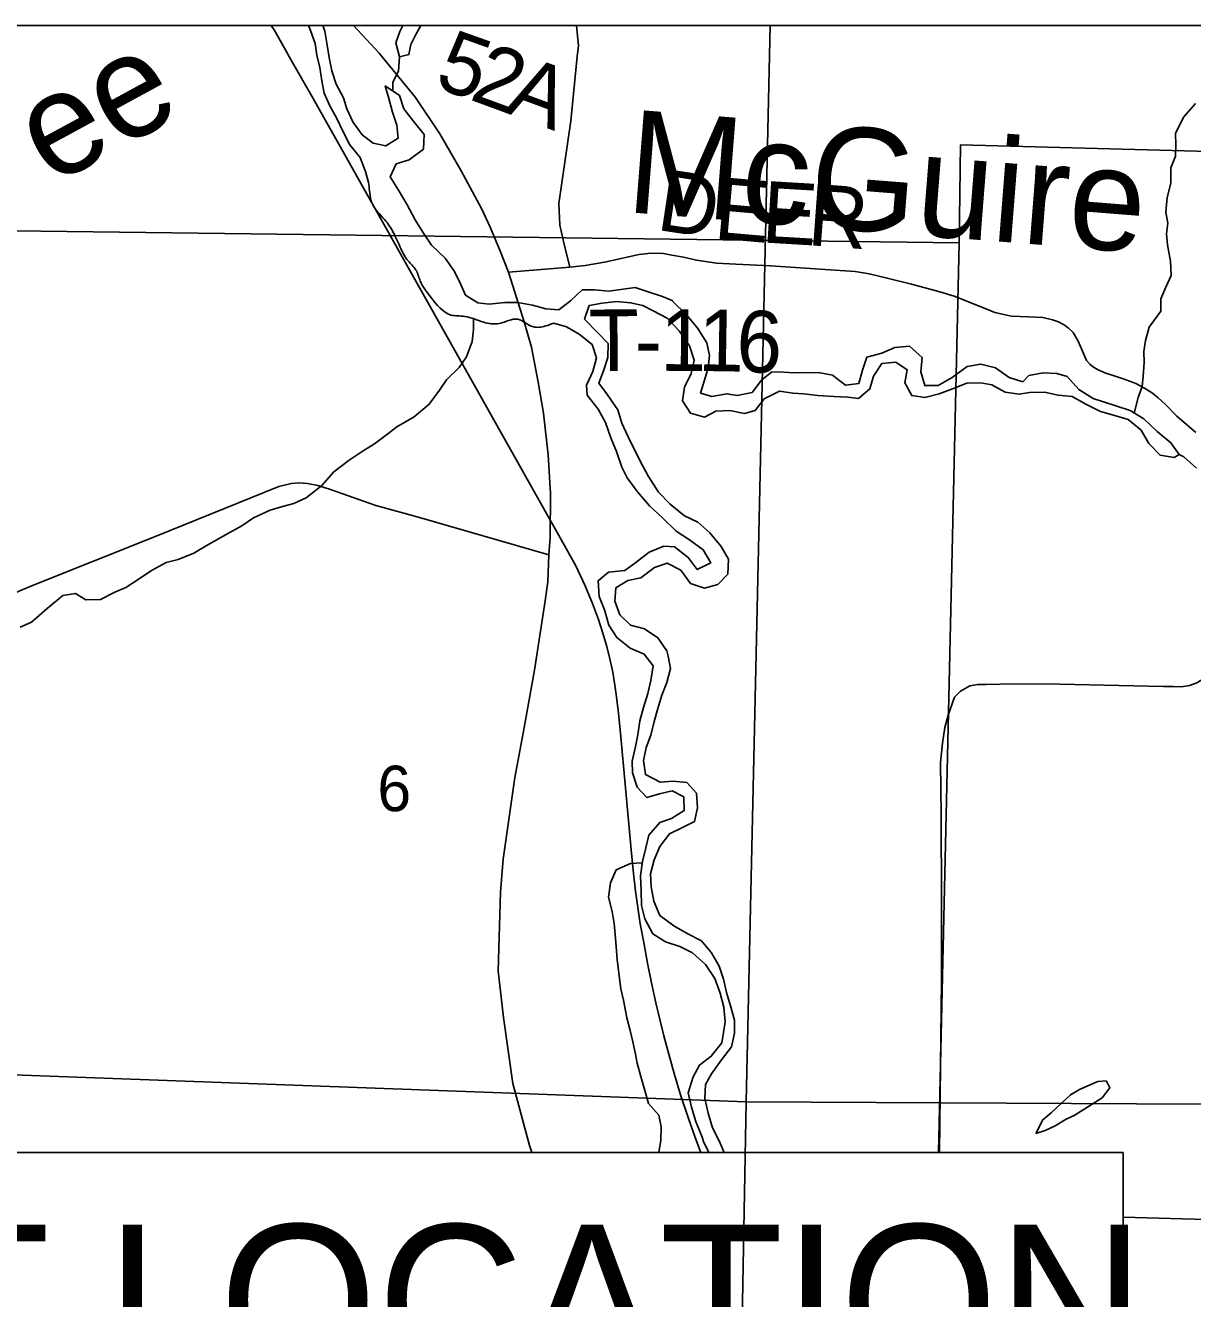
# Model space of a CAD drawing. Extents: x -19.9 to 41.9, y 0 to 32.3.
# Drawn here: x 3.386 to 4.462, y 19.727 to 20.9 of the extents above; entities that cross this region are included whole.
import ezdxf

# ---------------------------------------------------------------- set-up
doc = ezdxf.new("R2010")
doc.units = 0
for name, color, linetype in [('GM_X_Corporation', 7, 'Continuous'), ('GM_X_County_Road', 7, 'Continuous'), ('GM_X_County_Road_Text', 7, 'Continuous'), ('GM_X_Major_River', 7, 'Continuous'), ('GM_X_Major_River_Text', 7, 'Continuous'), ('GM_X_Minor_Lake', 7, 'Continuous'), ('GM_X_Minor_River', 7, 'Continuous'), ('GM_X_Rail_Line', 7, 'Continuous'), ('GM_X_Section', 7, 'Continuous'), ('GM_X_Section_Text', 7, 'Continuous'), ('GM_X_State_Route', 7, 'Continuous'), ('GM_X_Township_Road', 7, 'Continuous'), ('GM_X_Township_Road_Text', 7, 'Continuous'), ('SH_Data', 7, 'Continuous'), ('SH_Text', 7, 'Continuous')]:
    doc.layers.add(name, color=color, linetype=linetype)

msp = doc.modelspace()

# ---------------------------------------------------------------- linework, layer by layer
at = {"layer": 'GM_X_Corporation'}
for points in [[(8.9, 17.8974), (8.9, 20.9), (2.1, 20.9), (2.1, 17.918), (2.4715, 17.9106), (2.973, 17.9007), (3.7505, 17.884), (3.984, 17.879), (4.2613, 17.8672), (4.9169, 17.8392), (5.0192, 17.8403), (5.0257, 17.9637), (5.4954, 17.9559), (5.761, 17.9543), (5.9048, 17.9534), (6.2397, 17.9517), (6.2497, 17.9517), (6.3069, 17.9505), (6.7, 17.9422), (6.9468, 17.937), (7.3858, 17.9277), (7.5529, 17.9242), (7.9072, 17.9171)], [(4.0724, 20.9), (3.0583, 20.9), (3.0491, 19.9448), (4.0503, 19.9079)], [(4.5578, 20.9), (4.0724, 20.9), (4.0503, 19.9079), (5.0703, 19.9026), (5.0685, 20), (5.0885, 20.8933)], [(3.0491, 19.9448), (4.0503, 19.9079), (4.0319, 18.9009), (3.0393, 18.921)], [(4.0503, 19.9079), (5.0703, 19.9026), (5.0551, 18.9965), (5.0537, 18.8813), (4.0319, 18.9009)]]:
    msp.add_lwpolyline(points, close=True, dxfattribs=at)
msp.add_lwpolyline([(2.973, 17.9007), (3.7505, 17.884), (3.984, 17.879), (4.2613, 17.8672), (4.9169, 17.8392), (5.0192, 17.8403), (5.0257, 17.9637), (5.4954, 17.9559), (5.761, 17.9543), (5.9048, 17.9534), (6.2397, 17.9517), (6.2497, 17.9517), (6.3069, 17.9505), (6.7, 17.9422), (6.9468, 17.937), (7.3858, 17.9277), (7.5529, 17.9242), (7.9072, 17.9171), (7.9208, 18.3004), (7.9387, 18.9418), (7.9433, 19.1981), (7.9567, 19.9408), (7.9833, 20.9), (2.1, 20.9)], dxfattribs=at)
at = {"layer": 'GM_X_County_Road'}
msp.add_line((3.8935, 20.9), (3.894, 20.8998), dxfattribs=at)
for points in [[(3.894, 20.9), (3.894, 20.8998), (3.8956, 20.8815), (3.8946, 20.8713), (3.8887, 20.812), (3.8776, 20.736), (3.8784, 20.716), (3.883, 20.6958), (3.8867, 20.6812)], [(3.8867, 20.6812), (3.8877, 20.6773), (3.8313, 20.6725)], [(4.2286, 19.8611), (4.2303, 20.0199), (4.2305, 20.0932), (4.2301, 20.172), (4.2294, 20.2206), (4.2313, 20.2385), (4.2335, 20.2529), (4.2365, 20.2644), (4.2423, 20.281), (4.248, 20.2864), (4.2564, 20.2913), (4.264, 20.2926), (4.2714, 20.2927), (4.2841, 20.293), (4.3257, 20.2932), (4.4349, 20.2907), (4.4439, 20.2907), (4.4516, 20.2903), (4.4589, 20.2915), (4.4657, 20.294), (4.4728, 20.2984), (4.495, 20.3155), (4.529, 20.3478)]]:
    msp.add_lwpolyline(points, dxfattribs=at)
at = {"layer": 'GM_X_Major_River'}
for points in [[(3.6467, 20.9), (3.6487, 20.8955), (3.6531, 20.8834), (3.6544, 20.8725), (3.6572, 20.8611), (3.659, 20.849), (3.6614, 20.8377), (3.6666, 20.826), (3.6729, 20.8143), (3.6788, 20.8019), (3.685, 20.7899), (3.6944, 20.7783)], [(3.8777, 20.638), (3.8655, 20.6389), (3.8533, 20.6421), (3.8399, 20.6445), (3.8278, 20.6447), (3.8133, 20.643), (3.803, 20.6443), (3.7915, 20.6513), (3.7856, 20.6645), (3.7809, 20.6743), (3.7727, 20.6855), (3.7603, 20.6975), (3.7522, 20.7095), (3.7451, 20.7207), (3.7377, 20.7346), (3.7298, 20.7482), (3.722, 20.7605), (3.7275, 20.7724), (3.7396, 20.776), (3.7528, 20.7861), (3.7533, 20.7994), (3.7432, 20.8121), (3.7347, 20.8233), (3.7307, 20.8354), (3.7176, 20.8443), (3.7208, 20.8326), (3.7241, 20.8201), (3.7281, 20.8081), (3.7294, 20.796), (3.7181, 20.7889), (3.7063, 20.7914), (3.6963, 20.7992), (3.6877, 20.8112), (3.6822, 20.8232), (3.679, 20.8334), (3.6723, 20.8458), (3.6683, 20.8583), (3.6658, 20.8704), (3.6641, 20.8817), (3.662, 20.8946), (3.6601, 20.9)], [(3.9828, 20.6462), (3.9733, 20.6502), (3.961, 20.6542), (3.948, 20.6585), (3.9238, 20.6551), (3.9104, 20.6563), (3.899, 20.6562), (3.8882, 20.6461), (3.8777, 20.638)], [(3.9772, 20.3236), (3.969, 20.3356), (3.9567, 20.3438), (3.9437, 20.3474), (3.9337, 20.3567), (3.9293, 20.3695), (3.9302, 20.3817), (3.9411, 20.3883), (3.9533, 20.3908), (3.9657, 20.4005), (3.9774, 20.4044), (3.99, 20.3978), (3.999, 20.3855), (4.012, 20.3815), (4.0241, 20.3847), (4.0334, 20.3944), (4.0339, 20.408), (4.0273, 20.4197), (4.0168, 20.4324), (4.0056, 20.4421), (3.9934, 20.448), (3.9803, 20.4587), (3.9694, 20.4699), (3.9604, 20.4842), (3.9546, 20.4943), (3.9483, 20.5071), (3.9416, 20.5207), (3.9357, 20.5335), (3.932, 20.5456), (3.9223, 20.5594), (3.9145, 20.5703), (3.9189, 20.5818), (3.9229, 20.594), (3.923, 20.6069), (3.913, 20.6173), (3.9014, 20.6293), (3.9057, 20.6419), (3.9175, 20.6439), (3.9311, 20.6457), (3.9437, 20.6444), (3.9551, 20.6419), (3.9647, 20.6371), (3.9774, 20.6302), (3.9886, 20.6186), (3.998, 20.6047), (4.0024, 20.5915), (3.9995, 20.5793), (3.9933, 20.5667), (3.9916, 20.5541), (3.999, 20.5425), (4.012, 20.5389), (4.0222, 20.5444), (4.0351, 20.545), (4.0488, 20.5422), (4.0586, 20.545), (4.0668, 20.5558), (4.0811, 20.5628), (4.0933, 20.5612), (4.1032, 20.5606), (4.1162, 20.5589), (4.131, 20.558), (4.144, 20.5574), (4.1539, 20.5561), (4.1644, 20.565), (4.1676, 20.5768), (4.1754, 20.5883), (4.1883, 20.5897), (4.1987, 20.5826), (4.1966, 20.5705), (4.2029, 20.5588), (4.2151, 20.5571), (4.2283, 20.5604), (4.2404, 20.5651), (4.2536, 20.5703), (4.2665, 20.5705), (4.2768, 20.5688), (4.2891, 20.5621), (4.3021, 20.5601), (4.3115, 20.5618), (4.3252, 20.562), (4.3378, 20.5592), (4.3507, 20.5579), (4.3634, 20.5509), (4.3768, 20.5443), (4.389, 20.5407), (4.4024, 20.5367), (4.4144, 20.527), (4.4214, 20.5146), (4.4319, 20.5038), (4.4448, 20.5018), (4.4493, 20.5045)], [(4.3053, 20.5715), (4.2927, 20.5755), (4.28, 20.5844), (4.2666, 20.5879), (4.2541, 20.5858), (4.2402, 20.5754), (4.2274, 20.5683), (4.2149, 20.5681), (4.2112, 20.5806), (4.2125, 20.5939), (4.201, 20.6043), (4.1873, 20.6033), (4.1752, 20.5978), (4.1616, 20.5942), (4.1576, 20.5823), (4.154, 20.5701), (4.1419, 20.5684), (4.1299, 20.5777), (4.117, 20.5801), (4.0946, 20.5798), (4.0847, 20.5804), (4.074, 20.5806), (4.0643, 20.5732), (4.0557, 20.5617), (4.0421, 20.5588), (4.0325, 20.5605), (4.0185, 20.558), (4.0082, 20.5612), (4.0118, 20.5731), (4.0154, 20.5845), (4.0164, 20.5959), (4.0139, 20.6076), (4.0057, 20.6208), (3.9956, 20.6331), (3.9821, 20.6462), (3.9828, 20.6462)], [(3.8731, 20.6256), (3.8848, 20.6222), (3.8963, 20.6155), (3.9082, 20.6059), (3.9122, 20.5938), (3.909, 20.5812), (3.9032, 20.5686), (3.9037, 20.5591), (3.9138, 20.5464), (3.9205, 20.534), (3.9256, 20.52), (3.9308, 20.5072), (3.9356, 20.4929), (3.9407, 20.4831), (3.95, 20.47), (3.9613, 20.4573), (3.9733, 20.4461), (3.9856, 20.4338), (3.9979, 20.426), (4.0106, 20.4168), (4.0177, 20.4047), (4.0052, 20.3985), (3.9967, 20.4097), (3.9843, 20.4194), (3.9744, 20.42), (3.9609, 20.4144), (3.9485, 20.4051), (3.9383, 20.3977), (3.9235, 20.396), (3.9138, 20.3882), (3.9148, 20.3738), (3.9196, 20.3614), (3.9236, 20.3474), (3.931, 20.3358), (3.9433, 20.3261), (3.9563, 20.3206), (3.9645, 20.3098), (3.9625, 20.2961), (3.9596, 20.2843), (3.9557, 20.2713), (3.9524, 20.2591), (3.9504, 20.2462), (3.9479, 20.234), (3.9451, 20.2218), (3.9456, 20.2112), (3.9497, 20.198), (3.9586, 20.1883), (3.9703, 20.1919), (3.982, 20.1944), (3.9928, 20.1889), (3.993, 20.1763), (3.9813, 20.1689), (3.9707, 20.1653), (3.9607, 20.1538), (3.9578, 20.142), (3.9546, 20.1294), (3.9529, 20.1161), (3.9535, 20.1025), (3.9538, 20.0888), (3.957, 20.0767), (3.9641, 20.0628), (3.976, 20.0554), (3.989, 20.0511), (4.0009, 20.0452), (4.0128, 20.0344), (4.0214, 20.0217), (4.0262, 20.0081), (4.0298, 19.9952), (4.0308, 19.9816), (4.0295, 19.9717), (4.0277, 19.9622), (4.0181, 19.9499), (4.0072, 19.9417), (4.0013, 19.931), (3.9969, 19.9162), (3.9998, 19.9029), (4.0039, 19.8897), (4.0098, 19.8754)], [(4.4493, 20.5045), (4.4419, 20.5154), (4.4292, 20.5258), (4.4169, 20.5373), (4.4042, 20.5451), (4.3912, 20.5494), (4.3797, 20.553), (4.3702, 20.5563), (4.3571, 20.5644), (4.3463, 20.5764), (4.3367, 20.5792), (4.3241, 20.5798), (4.3109, 20.5773), (4.3053, 20.5715)], [(4.4493, 20.5045), (4.4539, 20.5023), (4.4655, 20.4919)], [(4.03, 19.8611), (4.0254, 19.8719), (4.0192, 19.8839), (4.0151, 19.8975), (4.0122, 19.9111), (4.0128, 19.924), (4.0183, 19.9336), (4.0276, 19.9466), (4.0369, 19.9586), (4.0394, 19.9711), (4.0395, 19.9833), (4.0359, 19.9965), (4.0323, 20.0086), (4.0294, 20.021), (4.0254, 20.0331), (4.0184, 20.0451), (4.009, 20.0563), (3.996, 20.063), (3.9837, 20.07), (3.9706, 20.0796), (3.9651, 20.0928), (3.9626, 20.106), (3.962, 20.1182), (3.9656, 20.1311), (3.9707, 20.1433), (3.9796, 20.1549), (3.991, 20.1604), (4.0026, 20.1663), (4.0055, 20.1788), (4.0045, 20.1925), (3.9956, 20.2022), (3.983, 20.2035), (3.9709, 20.2025), (3.9574, 20.2095), (3.9557, 20.2224), (3.9582, 20.2346), (3.9625, 20.246), (3.9654, 20.2586), (3.969, 20.2704), (3.9726, 20.2826), (3.9773, 20.2944), (3.9805, 20.3074), (3.9784, 20.3187), (3.9772, 20.3236)], [(4.0098, 19.8754), (4.011, 19.8713), (4.0158, 19.8611)]]:
    msp.add_lwpolyline(points, dxfattribs=at)
msp.add_spline([(3.6944, 20.7783), (3.7026, 20.7517), (3.7057, 20.7354), (3.7169, 20.7211), (3.725, 20.7091), (3.732, 20.6943), (3.7386, 20.6831), (3.7459, 20.6746), (3.7498, 20.6645), (3.7595, 20.6497), (3.7781, 20.6331), (3.7909, 20.6319), (3.8083, 20.6265), (3.8227, 20.6253), (3.8397, 20.6292), (3.8541, 20.6222), (3.8653, 20.623), (3.8731, 20.6256)], degree=3, dxfattribs=at)
at = {"layer": 'GM_X_Minor_Lake'}
for points in [[(3.7339, 20.9), (3.7309, 20.8943), (3.7272, 20.884), (3.7307, 20.8711)], [(3.7307, 20.8711), (3.7394, 20.8731), (3.7413, 20.8826), (3.7457, 20.8918), (3.7503, 20.9)], [(4.383, 19.9256), (4.3821, 19.9272), (4.3745, 19.9267), (4.3654, 19.9225), (4.3575, 19.9194), (4.3492, 19.9144), (4.3409, 19.9067), (4.3315, 19.8979), (4.3239, 19.8914), (4.3172, 19.8788)], [(4.3172, 19.8788), (4.3259, 19.8816), (4.335, 19.8858), (4.3452, 19.892), (4.3528, 19.8954), (4.3611, 19.9004), (4.3694, 19.9058), (4.3785, 19.9116), (4.3856, 19.9208), (4.383, 19.9256)]]:
    msp.add_lwpolyline(points, dxfattribs=at)
at = {"layer": 'GM_X_Minor_River'}
for points in [[(3.7246, 20.8395), (3.7245, 20.8476), (3.7297, 20.8579), (3.7307, 20.8711), (3.7272, 20.884), (3.7309, 20.8943), (3.7339, 20.9)], [(4.4079, 20.5428), (4.4115, 20.5572), (4.4152, 20.5671), (4.4163, 20.5766), (4.4173, 20.5895), (4.4168, 20.5994), (4.4183, 20.6096), (4.4219, 20.6218), (4.4324, 20.6367), (4.4327, 20.6481), (4.4372, 20.6587), (4.442, 20.6694), (4.4415, 20.6827), (4.4387, 20.6978), (4.4379, 20.708), (4.4389, 20.7179), (4.4373, 20.7278), (4.4384, 20.7414), (4.4417, 20.7547), (4.4419, 20.7688), (4.446, 20.7794), (4.4463, 20.7897), (4.4462, 20.8007), (4.4537, 20.8159), (4.4646, 20.8282)], [(3.7989, 20.6294), (3.799, 20.6198), (3.7976, 20.6088), (3.7924, 20.5947), (3.7857, 20.5848), (3.774, 20.5733), (3.7676, 20.5638), (3.7579, 20.5508), (3.7443, 20.5393), (3.7284, 20.5301), (3.7186, 20.5228), (3.7077, 20.5143), (3.6971, 20.5078), (3.6843, 20.4993), (3.6703, 20.4886), (3.659, 20.476), (3.6447, 20.4645), (3.6333, 20.4595), (3.6227, 20.4567), (3.6114, 20.4532), (3.5962, 20.4462), (3.5853, 20.4389), (3.5709, 20.4308), (3.5539, 20.4212), (3.5411, 20.4135), (3.5267, 20.4077), (3.5157, 20.4049), (3.5021, 20.3976), (3.4907, 20.3899), (3.4783, 20.3819), (3.4684, 20.3776), (3.4552, 20.371), (3.4415, 20.3705), (3.432, 20.3765), (3.4202, 20.3745), (3.4059, 20.3626), (3.3916, 20.35), (3.381, 20.3454)], [(3.9544, 20.1281), (3.9436, 20.1275), (3.9303, 20.1217), (3.9251, 20.1099), (3.9233, 20.0966), (3.9268, 20.0834), (3.9285, 20.0724), (3.9297, 20.0587), (3.9314, 20.039), (3.933, 20.0265), (3.9347, 20.0121), (3.9371, 20.0015), (3.9403, 19.9852), (3.9434, 19.9735), (3.9458, 19.9633), (3.9481, 19.9534), (3.9497, 19.9436), (3.9533, 19.9311), (3.9568, 19.9182), (3.9603, 19.9065), (3.9699, 19.8956), (3.9719, 19.885), (3.9716, 19.8724), (3.9698, 19.8614), (3.9697, 19.8611)]]:
    msp.add_lwpolyline(points, dxfattribs=at)
at = {"layer": 'GM_X_Rail_Line'}
msp.add_lwpolyline([(4.0084, 19.8611), (4.0082, 19.8618), (4.0031, 19.8758), (3.9972, 19.8926), (3.9899, 19.9145), (3.984, 19.9341), (3.979, 19.9519), (3.9744, 19.9687), (3.9711, 19.9827), (3.967, 19.9993), (3.9631, 20.0176), (3.9594, 20.0356), (3.9558, 20.0549), (3.9527, 20.072), (3.9505, 20.0871), (3.9484, 20.1021), (3.9464, 20.1185), (3.9443, 20.1402), (3.9387, 20.2008), (3.9347, 20.2443), (3.9327, 20.2661), (3.9309, 20.2812), (3.9293, 20.2919), (3.9273, 20.3038), (3.9245, 20.3162), (3.9219, 20.3277), (3.9182, 20.34), (3.9143, 20.3524), (3.9087, 20.3672), (3.9019, 20.3835), (3.8932, 20.4018), (3.8845, 20.418), (3.6512, 20.8328), (3.6322, 20.8659), (3.6219, 20.8841), (3.6151, 20.8959), (3.6124, 20.9)], dxfattribs=at)
at = {"layer": 'GM_X_Section'}
for points in [[(4.2277, 19.8611), (4.2465, 20.6998), (4.2479, 20.79), (5.0965, 20.7671), (5.0763, 19.7825), (4.3977, 19.8017)], [(3.2116, 19.8611), (3.2305, 20.7127), (4.2465, 20.6998), (4.2277, 19.8611)], [(4.3977, 19.8017), (5.0763, 19.7825), (5.0521, 18.7876), (4.2131, 18.8031), (4.2222, 19.3423)]]:
    msp.add_lwpolyline(points, dxfattribs=at)
at = {"layer": 'GM_X_State_Route'}
msp.add_lwpolyline([(3.6883, 20.9), (3.7121, 20.8744), (3.7456, 20.8337), (3.768, 20.8), (3.7876, 20.7659), (3.8066, 20.7307), (3.8144, 20.7142), (3.8232, 20.6929), (3.8313, 20.6725), (3.8457, 20.6268), (3.8523, 20.6035), (3.8586, 20.5713), (3.8636, 20.5426), (3.8679, 20.5043), (3.87, 20.4686), (3.8696, 20.4281), (3.8683, 20.412), (3.8674, 20.3871), (3.865, 20.3696), (3.8553, 20.3057), (3.8446, 20.2478), (3.8371, 20.2068), (3.8294, 20.153), (3.8262, 20.1316), (3.8238, 20.1011), (3.8217, 20.0285), (3.8265, 19.9855), (3.8351, 19.9249), (3.8505, 19.8676), (3.8528, 19.8611)], dxfattribs=at)
at = {"layer": 'GM_X_Township_Road'}
for points in [[(3.8877, 20.6773), (3.9019, 20.6787), (3.9198, 20.6818), (3.9517, 20.689), (3.9595, 20.6898), (3.9665, 20.6901), (3.9742, 20.6898), (3.9818, 20.6883), (3.9926, 20.6863), (4.0046, 20.6837), (4.0229, 20.6809), (4.0408, 20.6799), (4.0727, 20.6783), (4.1507, 20.6731), (4.1638, 20.671), (4.1804, 20.6671), (4.2027, 20.6614), (4.2287, 20.6546), (4.2421, 20.6504), (4.2705, 20.6392), (4.2796, 20.6355), (4.295, 20.6321), (4.3107, 20.6314), (4.3238, 20.6307), (4.3326, 20.6288), (4.3381, 20.6268), (4.3445, 20.6233), (4.3475, 20.621), (4.3516, 20.617), (4.3564, 20.6091), (4.3623, 20.5955), (4.3641, 20.5913), (4.367, 20.5877), (4.3704, 20.585), (4.3754, 20.5822), (4.3817, 20.5796), (4.3903, 20.5766), (4.3986, 20.5739), (4.4095, 20.5699), (4.4175, 20.5657), (4.4248, 20.5611), (4.4302, 20.5569), (4.4366, 20.5509), (4.4474, 20.54), (4.4648, 20.5249)], [(3.3457, 20.364), (3.3909, 20.3832), (3.5065, 20.4292), (3.6194, 20.4751), (3.6308, 20.4777), (3.638, 20.4783), (3.6458, 20.4777), (3.6554, 20.4759), (3.667, 20.4723), (3.709, 20.4575), (3.7471, 20.4471), (3.8683, 20.412)]]:
    msp.add_lwpolyline(points, dxfattribs=at)
at = {"layer": 'SH_Data'}
msp.add_line((2.1, 20.9), (8.9, 20.9), dxfattribs=at)
at = {"layer": 'SH_Text'}
msp.add_lwpolyline([(2.4893, 19.3423), (4.3977, 19.3423), (4.3977, 19.8611), (2.4893, 19.8611)], close=True, dxfattribs=at)

# ---------------------------------------------------------------- texts
at = {"layer": 'GM_X_County_Road_Text'}
for s, rotation, p in [('5', 340.4292, (3.7614, 20.8438)), ('2', 339.7555, (3.794, 20.8322)), ('A', 339.6669, (3.8265, 20.8202))]:
    msp.add_text(s, height=0.0568, rotation=rotation, dxfattribs=at).set_placement(p)
at = {"layer": 'GM_X_Major_River_Text'}
for s, height, rotation, p in [('ee', 0.0947, 28.5521, (3.4092, 20.7516)), ('McGuire', 0.09471, 355.4839, (3.9382, 20.7281))]:
    msp.add_text(s, height=height, rotation=rotation, dxfattribs=at).set_placement(p)
at = {"layer": 'GM_X_Section_Text'}
msp.add_text('6', height=0.0419, rotation=0, dxfattribs=at).set_placement((3.7103, 20.1758))
at = {"layer": 'GM_X_Township_Road_Text'}
for s, rotation, p in [('D', 351.466, (3.9664, 20.7118)), ('E', 355.0192, (4.0196, 20.7039)), ('E', 356.607, (4.0637, 20.7001)), ('R', 355.8885, (4.1059, 20.6976)), ('T', 0.3857, (3.9052, 20.5813)), ('1', 359.7684, (3.9709, 20.5817)), ('1', 359.0711, (4.0057, 20.5816)), ('6', 357.8972, (4.0404, 20.581)), ('-', 0.2342, (3.9476, 20.5816))]:
    msp.add_text(s, height=0.0568, rotation=rotation, dxfattribs=at).set_placement(p)
at = {"layer": 'SH_Text'}
msp.add_text('PROJECT LOCATION', height=0.14, dxfattribs=at).set_placement((2.5347, 19.6548))

doc.saveas('drawing.dxf')
